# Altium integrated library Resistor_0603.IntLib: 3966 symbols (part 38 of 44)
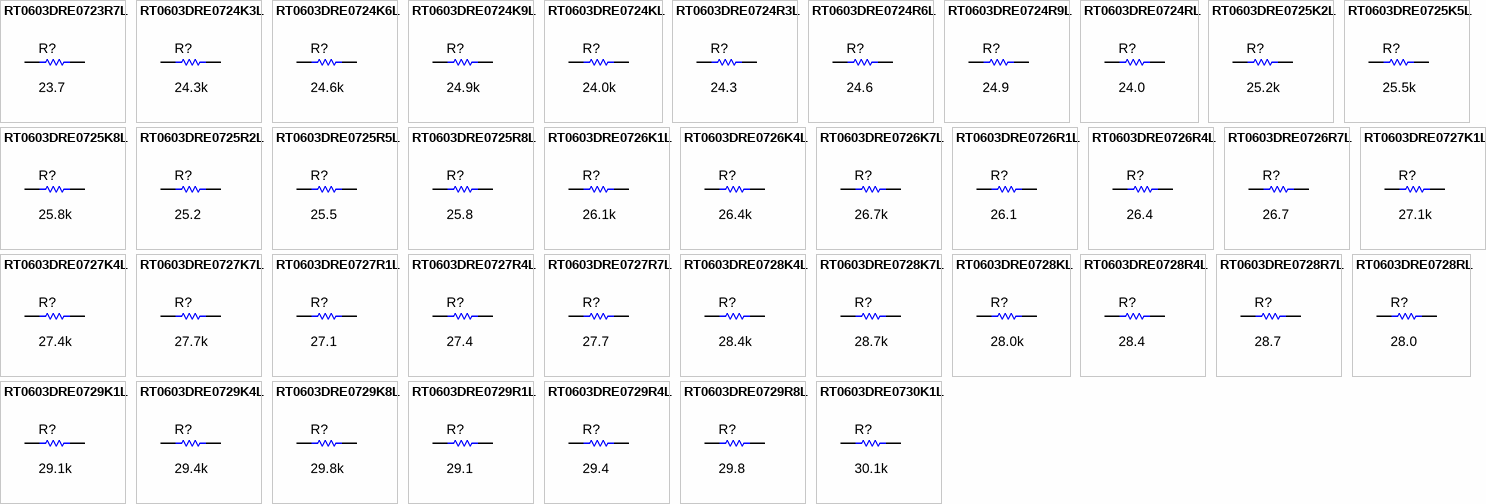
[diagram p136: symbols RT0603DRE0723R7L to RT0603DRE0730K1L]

## RT0603DRE0726R4L
designator R?  ValueDisplayed: 26.4  (hidden comment: RT0603DRE0726R4L)
RES, 26.4, 0.5%, 0.1 W, 0603; Manufacturer: Yageo America; CompType: Resistor; Value: 26.4; Value_Code: 26R4; Tolerance_%: 0.5; Power_W: 0.1; Value2: 0.1W; VDC_V: 75; TempCo: 50 ppm/C; SizeArea_mm2: 1.28; SizeX_mm: 1.6; SizeY_mm: 0.8; SizeZ_mm: 1; EIA_Code: E192; U/M: EA; AEC Category: Q200
signal-integrity model Resistor
simulation model Resistor
footprint 0603
footprint 0603M
footprint 0603L
footprint 0603_HV
footprint 0603S
pins: 1, 2

## RT0603DRE0726R7L
designator R?  ValueDisplayed: 26.7  (hidden comment: RT0603DRE0726R7L)
RES, 26.7, 0.5%, 0.1 W, 0603; Manufacturer: Yageo America; CompType: Resistor; Value: 26.7; Value_Code: 26R7; Tolerance_%: 0.5; Power_W: 0.1; Value2: 0.1W; VDC_V: 75; TempCo: 50 ppm/C; SizeArea_mm2: 1.28; SizeX_mm: 1.6; SizeY_mm: 0.8; SizeZ_mm: 1; EIA_Code: E192; U/M: EA; AEC Category: Q200
signal-integrity model Resistor
simulation model Resistor
footprint 0603
footprint 0603M
footprint 0603L
footprint 0603_HV
footprint 0603S
pins: 1, 2

## RT0603DRE0727K1L
designator R?  ValueDisplayed: 27.1k  (hidden comment: RT0603DRE0727K1L)
RES, 27.1 k, 0.5%, 0.1 W, 0603; Manufacturer: Yageo America; CompType: Resistor; Value: 27.1k; Res_ohm: 27100; Value_Code: 27k1; Tolerance_%: 0.5; Power_W: 0.1; Value2: 0.1W; VDC_V: 75; TempCo: 50 ppm/C; SizeArea_mm2: 1.28; SizeX_mm: 1.6; SizeY_mm: 0.8; SizeZ_mm: 1; EIA_Code: E192; U/M: EA; AEC Category: Q200
signal-integrity model Resistor
simulation model Resistor
footprint 0603
footprint 0603M
footprint 0603L
footprint 0603_HV
footprint 0603S
pins: 1, 2

## RT0603DRE0727K4L
designator R?  ValueDisplayed: 27.4k  (hidden comment: RT0603DRE0727K4L)
RES, 27.4 k, 0.5%, 0.1 W, 0603; Manufacturer: Yageo America; CompType: Resistor; Value: 27.4k; Res_ohm: 27400; Value_Code: 27k4; Tolerance_%: 0.5; Power_W: 0.1; Value2: 0.1W; VDC_V: 75; TempCo: 50 ppm/C; SizeArea_mm2: 1.28; SizeX_mm: 1.6; SizeY_mm: 0.8; SizeZ_mm: 1; EIA_Code: E192; U/M: EA; AEC Category: Q200
signal-integrity model Resistor
simulation model Resistor
footprint 0603
footprint 0603M
footprint 0603L
footprint 0603_HV
footprint 0603S
pins: 1, 2

## RT0603DRE0727K7L
designator R?  ValueDisplayed: 27.7k  (hidden comment: RT0603DRE0727K7L)
RES, 27.7 k, 0.5%, 0.1 W, 0603; Manufacturer: Yageo America; CompType: Resistor; Value: 27.7k; Res_ohm: 27700; Value_Code: 27k7; Tolerance_%: 0.5; Power_W: 0.1; Value2: 0.1W; VDC_V: 75; TempCo: 50 ppm/C; SizeArea_mm2: 1.28; SizeX_mm: 1.6; SizeY_mm: 0.8; SizeZ_mm: 1; EIA_Code: E192; U/M: EA; AEC Category: Q200
signal-integrity model Resistor
simulation model Resistor
footprint 0603
footprint 0603M
footprint 0603L
footprint 0603_HV
footprint 0603S
pins: 1, 2

## RT0603DRE0727R1L
designator R?  ValueDisplayed: 27.1  (hidden comment: RT0603DRE0727R1L)
RES, 27.1, 0.5%, 0.1 W, 0603; Manufacturer: Yageo America; CompType: Resistor; Value: 27.1; Value_Code: 27R1; Tolerance_%: 0.5; Power_W: 0.1; Value2: 0.1W; VDC_V: 75; TempCo: 50 ppm/C; SizeArea_mm2: 1.28; SizeX_mm: 1.6; SizeY_mm: 0.8; SizeZ_mm: 1; EIA_Code: E192; U/M: EA; AEC Category: Q200
signal-integrity model Resistor
simulation model Resistor
footprint 0603
footprint 0603M
footprint 0603L
footprint 0603_HV
footprint 0603S
pins: 1, 2

## RT0603DRE0727R4L
designator R?  ValueDisplayed: 27.4  (hidden comment: RT0603DRE0727R4L)
RES, 27.4, 0.5%, 0.1 W, 0603; Manufacturer: Yageo America; CompType: Resistor; Value: 27.4; Value_Code: 27R4; Tolerance_%: 0.5; Power_W: 0.1; Value2: 0.1W; VDC_V: 75; TempCo: 50 ppm/C; SizeArea_mm2: 1.28; SizeX_mm: 1.6; SizeY_mm: 0.8; SizeZ_mm: 1; EIA_Code: E192; U/M: EA; AEC Category: Q200
signal-integrity model Resistor
simulation model Resistor
footprint 0603
footprint 0603M
footprint 0603L
footprint 0603_HV
footprint 0603S
pins: 1, 2

## RT0603DRE0727R7L
designator R?  ValueDisplayed: 27.7  (hidden comment: RT0603DRE0727R7L)
RES, 27.7, 0.5%, 0.1 W, 0603; Manufacturer: Yageo America; CompType: Resistor; Value: 27.7; Value_Code: 27R7; Tolerance_%: 0.5; Power_W: 0.1; Value2: 0.1W; VDC_V: 75; TempCo: 50 ppm/C; SizeArea_mm2: 1.28; SizeX_mm: 1.6; SizeY_mm: 0.8; SizeZ_mm: 1; EIA_Code: E192; U/M: EA; AEC Category: Q200
signal-integrity model Resistor
simulation model Resistor
footprint 0603
footprint 0603M
footprint 0603L
footprint 0603_HV
footprint 0603S
pins: 1, 2

## RT0603DRE0728K4L
designator R?  ValueDisplayed: 28.4k  (hidden comment: RT0603DRE0728K4L)
RES, 28.4 k, 0.5%, 0.1 W, 0603; Manufacturer: Yageo America; CompType: Resistor; Value: 28.4k; Res_ohm: 28400; Value_Code: 28k4; Tolerance_%: 0.5; Power_W: 0.1; Value2: 0.1W; VDC_V: 75; TempCo: 50 ppm/C; SizeArea_mm2: 1.28; SizeX_mm: 1.6; SizeY_mm: 0.8; SizeZ_mm: 1; EIA_Code: E192; U/M: EA; AEC Category: Q200
signal-integrity model Resistor
simulation model Resistor
footprint 0603
footprint 0603M
footprint 0603L
footprint 0603_HV
footprint 0603S
pins: 1, 2

## RT0603DRE0728K7L
designator R?  ValueDisplayed: 28.7k  (hidden comment: RT0603DRE0728K7L)
RES, 28.7 k, 0.5%, 0.1 W, 0603; Manufacturer: Yageo America; CompType: Resistor; Value: 28.7k; Res_ohm: 28700; Value_Code: 28k7; Tolerance_%: 0.5; Power_W: 0.1; Value2: 0.1W; VDC_V: 75; TempCo: 50 ppm/C; SizeArea_mm2: 1.28; SizeX_mm: 1.6; SizeY_mm: 0.8; SizeZ_mm: 1; EIA_Code: E192; U/M: EA; AEC Category: Q200
signal-integrity model Resistor
simulation model Resistor
footprint 0603
footprint 0603M
footprint 0603L
footprint 0603_HV
footprint 0603S
pins: 1, 2

## RT0603DRE0728KL
designator R?  ValueDisplayed: 28.0k  (hidden comment: RT0603DRE0728KL)
RES, 28.0 k, 0.5%, 0.1 W, 0603; Manufacturer: Yageo America; CompType: Resistor; Value: 28.0k; Res_ohm: 28000; Value_Code: 28k0; Tolerance_%: 0.5; Power_W: 0.1; Value2: 0.1W; VDC_V: 75; TempCo: 50 ppm/C; SizeArea_mm2: 1.28; SizeX_mm: 1.6; SizeY_mm: 0.8; SizeZ_mm: 1; EIA_Code: E192; U/M: EA; AEC Category: Q200
signal-integrity model Resistor
simulation model Resistor
footprint 0603
footprint 0603M
footprint 0603L
footprint 0603_HV
footprint 0603S
pins: 1, 2

## RT0603DRE0728R4L
designator R?  ValueDisplayed: 28.4  (hidden comment: RT0603DRE0728R4L)
RES, 28.4, 0.5%, 0.1 W, 0603; Manufacturer: Yageo America; CompType: Resistor; Value: 28.4; Value_Code: 28R4; Tolerance_%: 0.5; Power_W: 0.1; Value2: 0.1W; VDC_V: 75; TempCo: 50 ppm/C; SizeArea_mm2: 1.28; SizeX_mm: 1.6; SizeY_mm: 0.8; SizeZ_mm: 1; EIA_Code: E192; U/M: EA; AEC Category: Q200
signal-integrity model Resistor
simulation model Resistor
footprint 0603
footprint 0603M
footprint 0603L
footprint 0603_HV
footprint 0603S
pins: 1, 2

## RT0603DRE0728R7L
designator R?  ValueDisplayed: 28.7  (hidden comment: RT0603DRE0728R7L)
RES, 28.7, 0.5%, 0.1 W, 0603; Manufacturer: Yageo America; CompType: Resistor; Value: 28.7; Value_Code: 28R7; Tolerance_%: 0.5; Power_W: 0.1; Value2: 0.1W; VDC_V: 75; TempCo: 50 ppm/C; SizeArea_mm2: 1.28; SizeX_mm: 1.6; SizeY_mm: 0.8; SizeZ_mm: 1; EIA_Code: E192; U/M: EA; AEC Category: Q200
signal-integrity model Resistor
simulation model Resistor
footprint 0603
footprint 0603M
footprint 0603L
footprint 0603_HV
footprint 0603S
pins: 1, 2

## RT0603DRE0728RL
designator R?  ValueDisplayed: 28.0  (hidden comment: RT0603DRE0728RL)
RES, 28.0, 0.5%, 0.1 W, 0603; Manufacturer: Yageo America; CompType: Resistor; Value: 28.0; Res_ohm: 28; Value_Code: 28R0; Tolerance_%: 0.5; Power_W: 0.1; Value2: 0.1W; VDC_V: 75; TempCo: 50 ppm/C; SizeArea_mm2: 1.28; SizeX_mm: 1.6; SizeY_mm: 0.8; SizeZ_mm: 1; EIA_Code: E192; U/M: EA; AEC Category: Q200
signal-integrity model Resistor
simulation model Resistor
footprint 0603
footprint 0603M
footprint 0603L
footprint 0603_HV
footprint 0603S
pins: 1, 2

## RT0603DRE0729K1L
designator R?  ValueDisplayed: 29.1k  (hidden comment: RT0603DRE0729K1L)
RES, 29.1 k, 0.5%, 0.1 W, 0603; Manufacturer: Yageo America; CompType: Resistor; Value: 29.1k; Res_ohm: 29100; Value_Code: 29k1; Tolerance_%: 0.5; Power_W: 0.1; Value2: 0.1W; VDC_V: 75; TempCo: 50 ppm/C; SizeArea_mm2: 1.28; SizeX_mm: 1.6; SizeY_mm: 0.8; SizeZ_mm: 1; EIA_Code: E192; U/M: EA; AEC Category: Q200
signal-integrity model Resistor
simulation model Resistor
footprint 0603
footprint 0603M
footprint 0603L
footprint 0603_HV
footprint 0603S
pins: 1, 2

## RT0603DRE0729K4L
designator R?  ValueDisplayed: 29.4k  (hidden comment: RT0603DRE0729K4L)
RES, 29.4 k, 0.5%, 0.1 W, 0603; Manufacturer: Yageo America; CompType: Resistor; Value: 29.4k; Res_ohm: 29400; Value_Code: 29k4; Tolerance_%: 0.5; Power_W: 0.1; Value2: 0.1W; VDC_V: 75; TempCo: 50 ppm/C; SizeArea_mm2: 1.28; SizeX_mm: 1.6; SizeY_mm: 0.8; SizeZ_mm: 1; EIA_Code: E192; U/M: EA; AEC Category: Q200
signal-integrity model Resistor
simulation model Resistor
footprint 0603
footprint 0603M
footprint 0603L
footprint 0603_HV
footprint 0603S
pins: 1, 2

## RT0603DRE0729K8L
designator R?  ValueDisplayed: 29.8k  (hidden comment: RT0603DRE0729K8L)
RES, 29.8 k, 0.5%, 0.1 W, 0603; Manufacturer: Yageo America; CompType: Resistor; Value: 29.8k; Res_ohm: 29800; Value_Code: 29k8; Tolerance_%: 0.5; Power_W: 0.1; Value2: 0.1W; VDC_V: 75; TempCo: 50 ppm/C; SizeArea_mm2: 1.28; SizeX_mm: 1.6; SizeY_mm: 0.8; SizeZ_mm: 1; EIA_Code: E192; U/M: EA; AEC Category: Q200
signal-integrity model Resistor
simulation model Resistor
footprint 0603
footprint 0603M
footprint 0603L
footprint 0603_HV
footprint 0603S
pins: 1, 2

## RT0603DRE0729R1L
designator R?  ValueDisplayed: 29.1  (hidden comment: RT0603DRE0729R1L)
RES, 29.1, 0.5%, 0.1 W, 0603; Manufacturer: Yageo America; CompType: Resistor; Value: 29.1; Value_Code: 29R1; Tolerance_%: 0.5; Power_W: 0.1; Value2: 0.1W; VDC_V: 75; TempCo: 50 ppm/C; SizeArea_mm2: 1.28; SizeX_mm: 1.6; SizeY_mm: 0.8; SizeZ_mm: 1; EIA_Code: E192; U/M: EA; AEC Category: Q200
signal-integrity model Resistor
simulation model Resistor
footprint 0603
footprint 0603M
footprint 0603L
footprint 0603_HV
footprint 0603S
pins: 1, 2

## RT0603DRE0729R4L
designator R?  ValueDisplayed: 29.4  (hidden comment: RT0603DRE0729R4L)
RES, 29.4, 0.5%, 0.1 W, 0603; Manufacturer: Yageo America; CompType: Resistor; Value: 29.4; Value_Code: 29R4; Tolerance_%: 0.5; Power_W: 0.1; Value2: 0.1W; VDC_V: 75; TempCo: 50 ppm/C; SizeArea_mm2: 1.28; SizeX_mm: 1.6; SizeY_mm: 0.8; SizeZ_mm: 1; EIA_Code: E192; U/M: EA; AEC Category: Q200
signal-integrity model Resistor
simulation model Resistor
footprint 0603
footprint 0603M
footprint 0603L
footprint 0603_HV
footprint 0603S
pins: 1, 2

## RT0603DRE0729R8L
designator R?  ValueDisplayed: 29.8  (hidden comment: RT0603DRE0729R8L)
RES, 29.8, 0.5%, 0.1 W, 0603; Manufacturer: Yageo America; CompType: Resistor; Value: 29.8; Value_Code: 29R8; Tolerance_%: 0.5; Power_W: 0.1; Value2: 0.1W; VDC_V: 75; TempCo: 50 ppm/C; SizeArea_mm2: 1.28; SizeX_mm: 1.6; SizeY_mm: 0.8; SizeZ_mm: 1; EIA_Code: E192; U/M: EA; AEC Category: Q200
signal-integrity model Resistor
simulation model Resistor
footprint 0603
footprint 0603M
footprint 0603L
footprint 0603_HV
footprint 0603S
pins: 1, 2

## RT0603DRE0730K1L
designator R?  ValueDisplayed: 30.1k  (hidden comment: RT0603DRE0730K1L)
RES, 30.1 k, 0.5%, 0.1 W, 0603; Manufacturer: Yageo America; CompType: Resistor; Value: 30.1k; Res_ohm: 30100; Value_Code: 30k1; Tolerance_%: 0.5; Power_W: 0.1; Value2: 0.1W; VDC_V: 75; TempCo: 50 ppm/C; SizeArea_mm2: 1.28; SizeX_mm: 1.6; SizeY_mm: 0.8; SizeZ_mm: 1; EIA_Code: E192; U/M: EA; AEC Category: Q200
signal-integrity model Resistor
simulation model Resistor
footprint 0603
footprint 0603M
footprint 0603L
footprint 0603_HV
footprint 0603S
pins: 1, 2

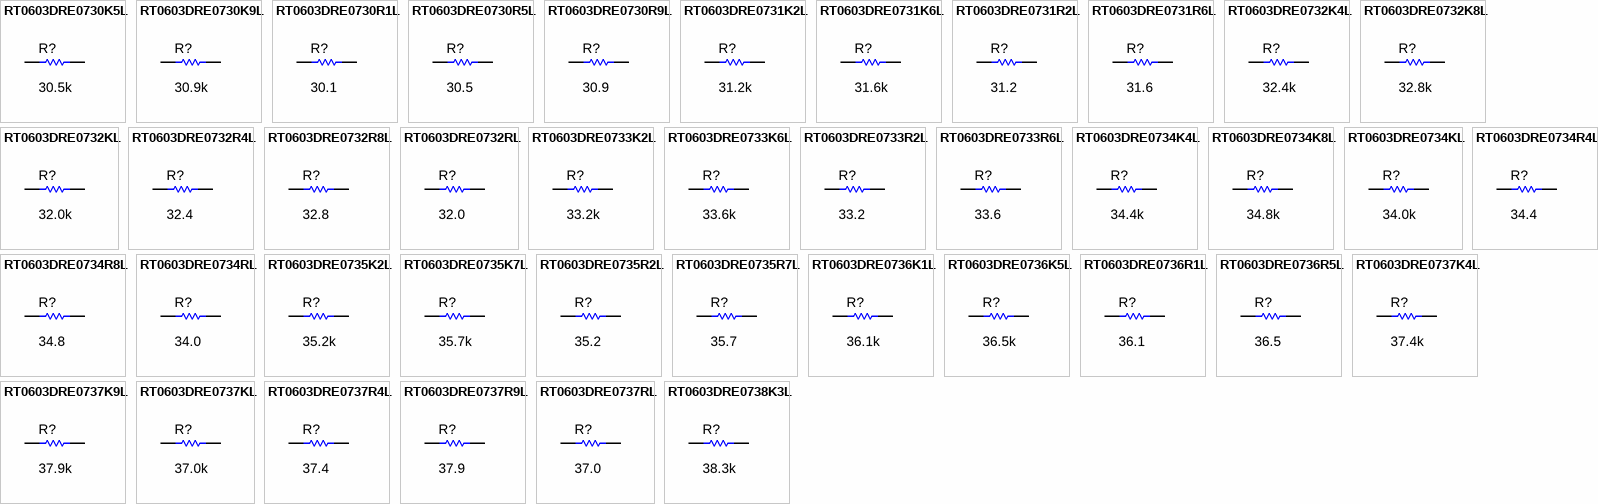
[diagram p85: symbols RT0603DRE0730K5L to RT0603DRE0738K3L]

## RT0603DRE0730K5L
designator R?  ValueDisplayed: 30.5k  (hidden comment: RT0603DRE0730K5L)
RES, 30.5 k, 0.5%, 0.1 W, 0603; Manufacturer: Yageo America; CompType: Resistor; Value: 30.5k; Res_ohm: 30500; Value_Code: 30k5; Tolerance_%: 0.5; Power_W: 0.1; Value2: 0.1W; VDC_V: 75; TempCo: 50 ppm/C; SizeArea_mm2: 1.28; SizeX_mm: 1.6; SizeY_mm: 0.8; SizeZ_mm: 1; EIA_Code: E192; U/M: EA; AEC Category: Q200
signal-integrity model Resistor
simulation model Resistor
footprint 0603
footprint 0603M
footprint 0603L
footprint 0603_HV
footprint 0603S
pins: 1, 2

## RT0603DRE0730K9L
designator R?  ValueDisplayed: 30.9k  (hidden comment: RT0603DRE0730K9L)
RES, 30.9 k, 0.5%, 0.1 W, 0603; Manufacturer: Yageo America; CompType: Resistor; Value: 30.9k; Res_ohm: 30900; Value_Code: 30k9; Tolerance_%: 0.5; Power_W: 0.1; Value2: 0.1W; VDC_V: 75; TempCo: 50 ppm/C; SizeArea_mm2: 1.28; SizeX_mm: 1.6; SizeY_mm: 0.8; SizeZ_mm: 1; EIA_Code: E192; U/M: EA; AEC Category: Q200
signal-integrity model Resistor
simulation model Resistor
footprint 0603
footprint 0603M
footprint 0603L
footprint 0603_HV
footprint 0603S
pins: 1, 2

## RT0603DRE0730R1L
designator R?  ValueDisplayed: 30.1  (hidden comment: RT0603DRE0730R1L)
RES, 30.1, 0.5%, 0.1 W, 0603; Manufacturer: Yageo America; CompType: Resistor; Value: 30.1; Value_Code: 30R1; Tolerance_%: 0.5; Power_W: 0.1; Value2: 0.1W; VDC_V: 75; TempCo: 50 ppm/C; SizeArea_mm2: 1.28; SizeX_mm: 1.6; SizeY_mm: 0.8; SizeZ_mm: 1; EIA_Code: E192; U/M: EA; AEC Category: Q200
signal-integrity model Resistor
simulation model Resistor
footprint 0603
footprint 0603M
footprint 0603L
footprint 0603_HV
footprint 0603S
pins: 1, 2

## RT0603DRE0730R5L
designator R?  ValueDisplayed: 30.5  (hidden comment: RT0603DRE0730R5L)
RES, 30.5, 0.5%, 0.1 W, 0603; Manufacturer: Yageo America; CompType: Resistor; Value: 30.5; Value_Code: 30R5; Tolerance_%: 0.5; Power_W: 0.1; Value2: 0.1W; VDC_V: 75; TempCo: 50 ppm/C; SizeArea_mm2: 1.28; SizeX_mm: 1.6; SizeY_mm: 0.8; SizeZ_mm: 1; EIA_Code: E192; U/M: EA; AEC Category: Q200
signal-integrity model Resistor
simulation model Resistor
footprint 0603
footprint 0603M
footprint 0603L
footprint 0603_HV
footprint 0603S
pins: 1, 2

## RT0603DRE0730R9L
designator R?  ValueDisplayed: 30.9  (hidden comment: RT0603DRE0730R9L)
RES, 30.9, 0.5%, 0.1 W, 0603; Manufacturer: Yageo America; CompType: Resistor; Value: 30.9; Value_Code: 30R9; Tolerance_%: 0.5; Power_W: 0.1; Value2: 0.1W; VDC_V: 75; TempCo: 50 ppm/C; SizeArea_mm2: 1.28; SizeX_mm: 1.6; SizeY_mm: 0.8; SizeZ_mm: 1; EIA_Code: E192; U/M: EA; AEC Category: Q200
signal-integrity model Resistor
simulation model Resistor
footprint 0603
footprint 0603M
footprint 0603L
footprint 0603_HV
footprint 0603S
pins: 1, 2

## RT0603DRE0731K2L
designator R?  ValueDisplayed: 31.2k  (hidden comment: RT0603DRE0731K2L)
RES, 31.2 k, 0.5%, 0.1 W, 0603; Manufacturer: Yageo America; CompType: Resistor; Value: 31.2k; Res_ohm: 31200; Value_Code: 31k2; Tolerance_%: 0.5; Power_W: 0.1; Value2: 0.1W; VDC_V: 75; TempCo: 50 ppm/C; SizeArea_mm2: 1.28; SizeX_mm: 1.6; SizeY_mm: 0.8; SizeZ_mm: 1; EIA_Code: E192; U/M: EA; AEC Category: Q200
signal-integrity model Resistor
simulation model Resistor
footprint 0603
footprint 0603M
footprint 0603L
footprint 0603_HV
footprint 0603S
pins: 1, 2

## RT0603DRE0731K6L
designator R?  ValueDisplayed: 31.6k  (hidden comment: RT0603DRE0731K6L)
RES, 31.6 k, 0.5%, 0.1 W, 0603; Manufacturer: Yageo America; CompType: Resistor; Value: 31.6k; Res_ohm: 31600; Value_Code: 31k6; Tolerance_%: 0.5; Power_W: 0.1; Value2: 0.1W; VDC_V: 75; TempCo: 50 ppm/C; SizeArea_mm2: 1.28; SizeX_mm: 1.6; SizeY_mm: 0.8; SizeZ_mm: 1; EIA_Code: E192; U/M: EA; AEC Category: Q200
signal-integrity model Resistor
simulation model Resistor
footprint 0603
footprint 0603M
footprint 0603L
footprint 0603_HV
footprint 0603S
pins: 1, 2

## RT0603DRE0731R2L
designator R?  ValueDisplayed: 31.2  (hidden comment: RT0603DRE0731R2L)
RES, 31.2, 0.5%, 0.1 W, 0603; Manufacturer: Yageo America; CompType: Resistor; Value: 31.2; Value_Code: 31R2; Tolerance_%: 0.5; Power_W: 0.1; Value2: 0.1W; VDC_V: 75; TempCo: 50 ppm/C; SizeArea_mm2: 1.28; SizeX_mm: 1.6; SizeY_mm: 0.8; SizeZ_mm: 1; EIA_Code: E192; U/M: EA; AEC Category: Q200
signal-integrity model Resistor
simulation model Resistor
footprint 0603
footprint 0603M
footprint 0603L
footprint 0603_HV
footprint 0603S
pins: 1, 2

## RT0603DRE0731R6L
designator R?  ValueDisplayed: 31.6  (hidden comment: RT0603DRE0731R6L)
RES, 31.6, 0.5%, 0.1 W, 0603; Manufacturer: Yageo America; CompType: Resistor; Value: 31.6; Value_Code: 31R6; Tolerance_%: 0.5; Power_W: 0.1; Value2: 0.1W; VDC_V: 75; TempCo: 50 ppm/C; SizeArea_mm2: 1.28; SizeX_mm: 1.6; SizeY_mm: 0.8; SizeZ_mm: 1; EIA_Code: E192; U/M: EA; AEC Category: Q200
signal-integrity model Resistor
simulation model Resistor
footprint 0603
footprint 0603M
footprint 0603L
footprint 0603_HV
footprint 0603S
pins: 1, 2

## RT0603DRE0732K4L
designator R?  ValueDisplayed: 32.4k  (hidden comment: RT0603DRE0732K4L)
RES, 32.4 k, 0.5%, 0.1 W, 0603; Manufacturer: Yageo America; CompType: Resistor; Value: 32.4k; Res_ohm: 32400; Value_Code: 32k4; Tolerance_%: 0.5; Power_W: 0.1; Value2: 0.1W; VDC_V: 75; TempCo: 50 ppm/C; SizeArea_mm2: 1.28; SizeX_mm: 1.6; SizeY_mm: 0.8; SizeZ_mm: 1; EIA_Code: E192; U/M: EA; AEC Category: Q200
signal-integrity model Resistor
simulation model Resistor
footprint 0603
footprint 0603M
footprint 0603L
footprint 0603_HV
footprint 0603S
pins: 1, 2

## RT0603DRE0732K8L
designator R?  ValueDisplayed: 32.8k  (hidden comment: RT0603DRE0732K8L)
RES, 32.8 k, 0.5%, 0.1 W, 0603; Manufacturer: Yageo America; CompType: Resistor; Value: 32.8k; Res_ohm: 32800; Value_Code: 32k8; Tolerance_%: 0.5; Power_W: 0.1; Value2: 0.1W; VDC_V: 75; TempCo: 50 ppm/C; SizeArea_mm2: 1.28; SizeX_mm: 1.6; SizeY_mm: 0.8; SizeZ_mm: 1; EIA_Code: E192; U/M: EA; AEC Category: Q200
signal-integrity model Resistor
simulation model Resistor
footprint 0603
footprint 0603M
footprint 0603L
footprint 0603_HV
footprint 0603S
pins: 1, 2

## RT0603DRE0732KL
designator R?  ValueDisplayed: 32.0k  (hidden comment: RT0603DRE0732KL)
RES, 32.0 k, 0.5%, 0.1 W, 0603; Manufacturer: Yageo America; CompType: Resistor; Value: 32.0k; Res_ohm: 32000; Value_Code: 32k0; Tolerance_%: 0.5; Power_W: 0.1; Value2: 0.1W; VDC_V: 75; TempCo: 50 ppm/C; SizeArea_mm2: 1.28; SizeX_mm: 1.6; SizeY_mm: 0.8; SizeZ_mm: 1; EIA_Code: E192; U/M: EA; AEC Category: Q200
signal-integrity model Resistor
simulation model Resistor
footprint 0603
footprint 0603M
footprint 0603L
footprint 0603_HV
footprint 0603S
pins: 1, 2

## RT0603DRE0732R4L
designator R?  ValueDisplayed: 32.4  (hidden comment: RT0603DRE0732R4L)
RES, 32.4, 0.5%, 0.1 W, 0603; Manufacturer: Yageo America; CompType: Resistor; Value: 32.4; Value_Code: 32R4; Tolerance_%: 0.5; Power_W: 0.1; Value2: 0.1W; VDC_V: 75; TempCo: 50 ppm/C; SizeArea_mm2: 1.28; SizeX_mm: 1.6; SizeY_mm: 0.8; SizeZ_mm: 1; EIA_Code: E192; U/M: EA; AEC Category: Q200
signal-integrity model Resistor
simulation model Resistor
footprint 0603
footprint 0603M
footprint 0603L
footprint 0603_HV
footprint 0603S
pins: 1, 2

## RT0603DRE0732R8L
designator R?  ValueDisplayed: 32.8  (hidden comment: RT0603DRE0732R8L)
RES, 32.8, 0.5%, 0.1 W, 0603; Manufacturer: Yageo America; CompType: Resistor; Value: 32.8; Value_Code: 32R8; Tolerance_%: 0.5; Power_W: 0.1; Value2: 0.1W; VDC_V: 75; TempCo: 50 ppm/C; SizeArea_mm2: 1.28; SizeX_mm: 1.6; SizeY_mm: 0.8; SizeZ_mm: 1; EIA_Code: E192; U/M: EA; AEC Category: Q200
signal-integrity model Resistor
simulation model Resistor
footprint 0603
footprint 0603M
footprint 0603L
footprint 0603_HV
footprint 0603S
pins: 1, 2

## RT0603DRE0732RL
designator R?  ValueDisplayed: 32.0  (hidden comment: RT0603DRE0732RL)
RES, 32.0, 0.5%, 0.1 W, 0603; Manufacturer: Yageo America; CompType: Resistor; Value: 32.0; Res_ohm: 32; Value_Code: 32R0; Tolerance_%: 0.5; Power_W: 0.1; Value2: 0.1W; VDC_V: 75; TempCo: 50 ppm/C; SizeArea_mm2: 1.28; SizeX_mm: 1.6; SizeY_mm: 0.8; SizeZ_mm: 1; EIA_Code: E192; U/M: EA; AEC Category: Q200
signal-integrity model Resistor
simulation model Resistor
footprint 0603
footprint 0603M
footprint 0603L
footprint 0603_HV
footprint 0603S
pins: 1, 2

## RT0603DRE0733K2L
designator R?  ValueDisplayed: 33.2k  (hidden comment: RT0603DRE0733K2L)
RES, 33.2 k, 0.5%, 0.1 W, 0603; Manufacturer: Yageo America; CompType: Resistor; Value: 33.2k; Res_ohm: 33200; Value_Code: 33k2; Tolerance_%: 0.5; Power_W: 0.1; Value2: 0.1W; VDC_V: 75; TempCo: 50 ppm/C; SizeArea_mm2: 1.28; SizeX_mm: 1.6; SizeY_mm: 0.8; SizeZ_mm: 1; EIA_Code: E192; U/M: EA; AEC Category: Q200
signal-integrity model Resistor
simulation model Resistor
footprint 0603
footprint 0603M
footprint 0603L
footprint 0603_HV
footprint 0603S
pins: 1, 2

## RT0603DRE0733K6L
designator R?  ValueDisplayed: 33.6k  (hidden comment: RT0603DRE0733K6L)
RES, 33.6 k, 0.5%, 0.1 W, 0603; Manufacturer: Yageo America; CompType: Resistor; Value: 33.6k; Res_ohm: 33600; Value_Code: 33k6; Tolerance_%: 0.5; Power_W: 0.1; Value2: 0.1W; VDC_V: 75; TempCo: 50 ppm/C; SizeArea_mm2: 1.28; SizeX_mm: 1.6; SizeY_mm: 0.8; SizeZ_mm: 1; EIA_Code: E192; U/M: EA; AEC Category: Q200
signal-integrity model Resistor
simulation model Resistor
footprint 0603
footprint 0603M
footprint 0603L
footprint 0603_HV
footprint 0603S
pins: 1, 2

## RT0603DRE0733R2L
designator R?  ValueDisplayed: 33.2  (hidden comment: RT0603DRE0733R2L)
RES, 33.2, 0.5%, 0.1 W, 0603; Manufacturer: Yageo America; CompType: Resistor; Value: 33.2; Value_Code: 33R2; Tolerance_%: 0.5; Power_W: 0.1; Value2: 0.1W; VDC_V: 75; TempCo: 50 ppm/C; SizeArea_mm2: 1.28; SizeX_mm: 1.6; SizeY_mm: 0.8; SizeZ_mm: 1; EIA_Code: E192; U/M: EA; AEC Category: Q200
signal-integrity model Resistor
simulation model Resistor
footprint 0603
footprint 0603M
footprint 0603L
footprint 0603_HV
footprint 0603S
pins: 1, 2

## RT0603DRE0733R6L
designator R?  ValueDisplayed: 33.6  (hidden comment: RT0603DRE0733R6L)
RES, 33.6, 0.5%, 0.1 W, 0603; Manufacturer: Yageo America; CompType: Resistor; Value: 33.6; Value_Code: 33R6; Tolerance_%: 0.5; Power_W: 0.1; Value2: 0.1W; VDC_V: 75; TempCo: 50 ppm/C; SizeArea_mm2: 1.28; SizeX_mm: 1.6; SizeY_mm: 0.8; SizeZ_mm: 1; EIA_Code: E192; U/M: EA; AEC Category: Q200
signal-integrity model Resistor
simulation model Resistor
footprint 0603
footprint 0603M
footprint 0603L
footprint 0603_HV
footprint 0603S
pins: 1, 2

## RT0603DRE0734K4L
designator R?  ValueDisplayed: 34.4k  (hidden comment: RT0603DRE0734K4L)
RES, 34.4 k, 0.5%, 0.1 W, 0603; Manufacturer: Yageo America; CompType: Resistor; Value: 34.4k; Res_ohm: 34400; Value_Code: 34k4; Tolerance_%: 0.5; Power_W: 0.1; Value2: 0.1W; VDC_V: 75; TempCo: 50 ppm/C; SizeArea_mm2: 1.28; SizeX_mm: 1.6; SizeY_mm: 0.8; SizeZ_mm: 1; EIA_Code: E192; U/M: EA; AEC Category: Q200
signal-integrity model Resistor
simulation model Resistor
footprint 0603
footprint 0603M
footprint 0603L
footprint 0603_HV
footprint 0603S
pins: 1, 2

## RT0603DRE0734K8L
designator R?  ValueDisplayed: 34.8k  (hidden comment: RT0603DRE0734K8L)
RES, 34.8 k, 0.5%, 0.1 W, 0603; Manufacturer: Yageo America; CompType: Resistor; Value: 34.8k; Res_ohm: 34800; Value_Code: 34k8; Tolerance_%: 0.5; Power_W: 0.1; Value2: 0.1W; VDC_V: 75; TempCo: 50 ppm/C; SizeArea_mm2: 1.28; SizeX_mm: 1.6; SizeY_mm: 0.8; SizeZ_mm: 1; EIA_Code: E192; U/M: EA; AEC Category: Q200
signal-integrity model Resistor
simulation model Resistor
footprint 0603
footprint 0603M
footprint 0603L
footprint 0603_HV
footprint 0603S
pins: 1, 2

## RT0603DRE0734KL
designator R?  ValueDisplayed: 34.0k  (hidden comment: RT0603DRE0734KL)
RES, 34.0 k, 0.5%, 0.1 W, 0603; Manufacturer: Yageo America; CompType: Resistor; Value: 34.0k; Res_ohm: 34000; Value_Code: 34k0; Tolerance_%: 0.5; Power_W: 0.1; Value2: 0.1W; VDC_V: 75; TempCo: 50 ppm/C; SizeArea_mm2: 1.28; SizeX_mm: 1.6; SizeY_mm: 0.8; SizeZ_mm: 1; EIA_Code: E192; U/M: EA; AEC Category: Q200
signal-integrity model Resistor
simulation model Resistor
footprint 0603
footprint 0603M
footprint 0603L
footprint 0603_HV
footprint 0603S
pins: 1, 2

## RT0603DRE0734R4L
designator R?  ValueDisplayed: 34.4  (hidden comment: RT0603DRE0734R4L)
RES, 34.4, 0.5%, 0.1 W, 0603; Manufacturer: Yageo America; CompType: Resistor; Value: 34.4; Value_Code: 34R4; Tolerance_%: 0.5; Power_W: 0.1; Value2: 0.1W; VDC_V: 75; TempCo: 50 ppm/C; SizeArea_mm2: 1.28; SizeX_mm: 1.6; SizeY_mm: 0.8; SizeZ_mm: 1; EIA_Code: E192; U/M: EA; AEC Category: Q200
signal-integrity model Resistor
simulation model Resistor
footprint 0603
footprint 0603M
footprint 0603L
footprint 0603_HV
footprint 0603S
pins: 1, 2

## RT0603DRE0734R8L
designator R?  ValueDisplayed: 34.8  (hidden comment: RT0603DRE0734R8L)
RES, 34.8, 0.5%, 0.1 W, 0603; Manufacturer: Yageo America; CompType: Resistor; Value: 34.8; Value_Code: 34R8; Tolerance_%: 0.5; Power_W: 0.1; Value2: 0.1W; VDC_V: 75; TempCo: 50 ppm/C; SizeArea_mm2: 1.28; SizeX_mm: 1.6; SizeY_mm: 0.8; SizeZ_mm: 1; EIA_Code: E192; U/M: EA; AEC Category: Q200
signal-integrity model Resistor
simulation model Resistor
footprint 0603
footprint 0603M
footprint 0603L
footprint 0603_HV
footprint 0603S
pins: 1, 2

## RT0603DRE0734RL
designator R?  ValueDisplayed: 34.0  (hidden comment: RT0603DRE0734RL)
RES, 34.0, 0.5%, 0.1 W, 0603; Manufacturer: Yageo America; CompType: Resistor; Value: 34.0; Res_ohm: 34; Value_Code: 34R0; Tolerance_%: 0.5; Power_W: 0.1; Value2: 0.1W; VDC_V: 75; TempCo: 50 ppm/C; SizeArea_mm2: 1.28; SizeX_mm: 1.6; SizeY_mm: 0.8; SizeZ_mm: 1; EIA_Code: E192; U/M: EA; AEC Category: Q200
signal-integrity model Resistor
simulation model Resistor
footprint 0603
footprint 0603M
footprint 0603L
footprint 0603_HV
footprint 0603S
pins: 1, 2

## RT0603DRE0735K2L
designator R?  ValueDisplayed: 35.2k  (hidden comment: RT0603DRE0735K2L)
RES, 35.2 k, 0.5%, 0.1 W, 0603; Manufacturer: Yageo America; CompType: Resistor; Value: 35.2k; Res_ohm: 35200; Value_Code: 35k2; Tolerance_%: 0.5; Power_W: 0.1; Value2: 0.1W; VDC_V: 75; TempCo: 50 ppm/C; SizeArea_mm2: 1.28; SizeX_mm: 1.6; SizeY_mm: 0.8; SizeZ_mm: 1; EIA_Code: E192; U/M: EA; AEC Category: Q200
signal-integrity model Resistor
simulation model Resistor
footprint 0603
footprint 0603M
footprint 0603L
footprint 0603_HV
footprint 0603S
pins: 1, 2

## RT0603DRE0735K7L
designator R?  ValueDisplayed: 35.7k  (hidden comment: RT0603DRE0735K7L)
RES, 35.7 k, 0.5%, 0.1 W, 0603; Manufacturer: Yageo America; CompType: Resistor; Value: 35.7k; Res_ohm: 35700; Value_Code: 35k7; Tolerance_%: 0.5; Power_W: 0.1; Value2: 0.1W; VDC_V: 75; TempCo: 50 ppm/C; SizeArea_mm2: 1.28; SizeX_mm: 1.6; SizeY_mm: 0.8; SizeZ_mm: 1; EIA_Code: E192; U/M: EA; AEC Category: Q200
signal-integrity model Resistor
simulation model Resistor
footprint 0603
footprint 0603M
footprint 0603L
footprint 0603_HV
footprint 0603S
pins: 1, 2

## RT0603DRE0735R2L
designator R?  ValueDisplayed: 35.2  (hidden comment: RT0603DRE0735R2L)
RES, 35.2, 0.5%, 0.1 W, 0603; Manufacturer: Yageo America; CompType: Resistor; Value: 35.2; Value_Code: 35R2; Tolerance_%: 0.5; Power_W: 0.1; Value2: 0.1W; VDC_V: 75; TempCo: 50 ppm/C; SizeArea_mm2: 1.28; SizeX_mm: 1.6; SizeY_mm: 0.8; SizeZ_mm: 1; EIA_Code: E192; U/M: EA; AEC Category: Q200
signal-integrity model Resistor
simulation model Resistor
footprint 0603
footprint 0603M
footprint 0603L
footprint 0603_HV
footprint 0603S
pins: 1, 2

## RT0603DRE0735R7L
designator R?  ValueDisplayed: 35.7  (hidden comment: RT0603DRE0735R7L)
RES, 35.7, 0.5%, 0.1 W, 0603; Manufacturer: Yageo America; CompType: Resistor; Value: 35.7; Value_Code: 35R7; Tolerance_%: 0.5; Power_W: 0.1; Value2: 0.1W; VDC_V: 75; TempCo: 50 ppm/C; SizeArea_mm2: 1.28; SizeX_mm: 1.6; SizeY_mm: 0.8; SizeZ_mm: 1; EIA_Code: E192; U/M: EA; AEC Category: Q200
signal-integrity model Resistor
simulation model Resistor
footprint 0603
footprint 0603M
footprint 0603L
footprint 0603_HV
footprint 0603S
pins: 1, 2

## RT0603DRE0736K1L
designator R?  ValueDisplayed: 36.1k  (hidden comment: RT0603DRE0736K1L)
RES, 36.1 k, 0.5%, 0.1 W, 0603; Manufacturer: Yageo America; CompType: Resistor; Value: 36.1k; Res_ohm: 36100; Value_Code: 36k1; Tolerance_%: 0.5; Power_W: 0.1; Value2: 0.1W; VDC_V: 75; TempCo: 50 ppm/C; SizeArea_mm2: 1.28; SizeX_mm: 1.6; SizeY_mm: 0.8; SizeZ_mm: 1; EIA_Code: E192; U/M: EA; AEC Category: Q200
signal-integrity model Resistor
simulation model Resistor
footprint 0603
footprint 0603M
footprint 0603L
footprint 0603_HV
footprint 0603S
pins: 1, 2

## RT0603DRE0736K5L
designator R?  ValueDisplayed: 36.5k  (hidden comment: RT0603DRE0736K5L)
RES, 36.5 k, 0.5%, 0.1 W, 0603; Manufacturer: Yageo America; CompType: Resistor; Value: 36.5k; Res_ohm: 36500; Value_Code: 36k5; Tolerance_%: 0.5; Power_W: 0.1; Value2: 0.1W; VDC_V: 75; TempCo: 50 ppm/C; SizeArea_mm2: 1.28; SizeX_mm: 1.6; SizeY_mm: 0.8; SizeZ_mm: 1; EIA_Code: E192; U/M: EA; AEC Category: Q200
signal-integrity model Resistor
simulation model Resistor
footprint 0603
footprint 0603M
footprint 0603L
footprint 0603_HV
footprint 0603S
pins: 1, 2

## RT0603DRE0736R1L
designator R?  ValueDisplayed: 36.1  (hidden comment: RT0603DRE0736R1L)
RES, 36.1, 0.5%, 0.1 W, 0603; Manufacturer: Yageo America; CompType: Resistor; Value: 36.1; Value_Code: 36R1; Tolerance_%: 0.5; Power_W: 0.1; Value2: 0.1W; VDC_V: 75; TempCo: 50 ppm/C; SizeArea_mm2: 1.28; SizeX_mm: 1.6; SizeY_mm: 0.8; SizeZ_mm: 1; EIA_Code: E192; U/M: EA; AEC Category: Q200
signal-integrity model Resistor
simulation model Resistor
footprint 0603
footprint 0603M
footprint 0603L
footprint 0603_HV
footprint 0603S
pins: 1, 2

## RT0603DRE0736R5L
designator R?  ValueDisplayed: 36.5  (hidden comment: RT0603DRE0736R5L)
RES, 36.5, 0.5%, 0.1 W, 0603; Manufacturer: Yageo America; CompType: Resistor; Value: 36.5; Value_Code: 36R5; Tolerance_%: 0.5; Power_W: 0.1; Value2: 0.1W; VDC_V: 75; TempCo: 50 ppm/C; SizeArea_mm2: 1.28; SizeX_mm: 1.6; SizeY_mm: 0.8; SizeZ_mm: 1; EIA_Code: E192; U/M: EA; AEC Category: Q200
signal-integrity model Resistor
simulation model Resistor
footprint 0603
footprint 0603M
footprint 0603L
footprint 0603_HV
footprint 0603S
pins: 1, 2

## RT0603DRE0737K4L
designator R?  ValueDisplayed: 37.4k  (hidden comment: RT0603DRE0737K4L)
RES, 37.4 k, 0.5%, 0.1 W, 0603; Manufacturer: Yageo America; CompType: Resistor; Value: 37.4k; Res_ohm: 37400; Value_Code: 37k4; Tolerance_%: 0.5; Power_W: 0.1; Value2: 0.1W; VDC_V: 75; TempCo: 50 ppm/C; SizeArea_mm2: 1.28; SizeX_mm: 1.6; SizeY_mm: 0.8; SizeZ_mm: 1; EIA_Code: E192; U/M: EA; AEC Category: Q200
signal-integrity model Resistor
simulation model Resistor
footprint 0603
footprint 0603M
footprint 0603L
footprint 0603_HV
footprint 0603S
pins: 1, 2

## RT0603DRE0737K9L
designator R?  ValueDisplayed: 37.9k  (hidden comment: RT0603DRE0737K9L)
RES, 37.9 k, 0.5%, 0.1 W, 0603; Manufacturer: Yageo America; CompType: Resistor; Value: 37.9k; Res_ohm: 37900; Value_Code: 37k9; Tolerance_%: 0.5; Power_W: 0.1; Value2: 0.1W; VDC_V: 75; TempCo: 50 ppm/C; SizeArea_mm2: 1.28; SizeX_mm: 1.6; SizeY_mm: 0.8; SizeZ_mm: 1; EIA_Code: E192; U/M: EA; AEC Category: Q200
signal-integrity model Resistor
simulation model Resistor
footprint 0603
footprint 0603M
footprint 0603L
footprint 0603_HV
footprint 0603S
pins: 1, 2

## RT0603DRE0737KL
designator R?  ValueDisplayed: 37.0k  (hidden comment: RT0603DRE0737KL)
RES, 37.0 k, 0.5%, 0.1 W, 0603; Manufacturer: Yageo America; CompType: Resistor; Value: 37.0k; Res_ohm: 37000; Value_Code: 37k0; Tolerance_%: 0.5; Power_W: 0.1; Value2: 0.1W; VDC_V: 75; TempCo: 50 ppm/C; SizeArea_mm2: 1.28; SizeX_mm: 1.6; SizeY_mm: 0.8; SizeZ_mm: 1; EIA_Code: E192; U/M: EA; AEC Category: Q200
signal-integrity model Resistor
simulation model Resistor
footprint 0603
footprint 0603M
footprint 0603L
footprint 0603_HV
footprint 0603S
pins: 1, 2

## RT0603DRE0737R4L
designator R?  ValueDisplayed: 37.4  (hidden comment: RT0603DRE0737R4L)
RES, 37.4, 0.5%, 0.1 W, 0603; Manufacturer: Yageo America; CompType: Resistor; Value: 37.4; Value_Code: 37R4; Tolerance_%: 0.5; Power_W: 0.1; Value2: 0.1W; VDC_V: 75; TempCo: 50 ppm/C; SizeArea_mm2: 1.28; SizeX_mm: 1.6; SizeY_mm: 0.8; SizeZ_mm: 1; EIA_Code: E192; U/M: EA; AEC Category: Q200
signal-integrity model Resistor
simulation model Resistor
footprint 0603
footprint 0603M
footprint 0603L
footprint 0603_HV
footprint 0603S
pins: 1, 2

## RT0603DRE0737R9L
designator R?  ValueDisplayed: 37.9  (hidden comment: RT0603DRE0737R9L)
RES, 37.9, 0.5%, 0.1 W, 0603; Manufacturer: Yageo America; CompType: Resistor; Value: 37.9; Value_Code: 37R9; Tolerance_%: 0.5; Power_W: 0.1; Value2: 0.1W; VDC_V: 75; TempCo: 50 ppm/C; SizeArea_mm2: 1.28; SizeX_mm: 1.6; SizeY_mm: 0.8; SizeZ_mm: 1; EIA_Code: E192; U/M: EA; AEC Category: Q200
signal-integrity model Resistor
simulation model Resistor
footprint 0603
footprint 0603M
footprint 0603L
footprint 0603_HV
footprint 0603S
pins: 1, 2

## RT0603DRE0737RL
designator R?  ValueDisplayed: 37.0  (hidden comment: RT0603DRE0737RL)
RES, 37.0, 0.5%, 0.1 W, 0603; Manufacturer: Yageo America; CompType: Resistor; Value: 37.0; Res_ohm: 37; Value_Code: 37R0; Tolerance_%: 0.5; Power_W: 0.1; Value2: 0.1W; VDC_V: 75; TempCo: 50 ppm/C; SizeArea_mm2: 1.28; SizeX_mm: 1.6; SizeY_mm: 0.8; SizeZ_mm: 1; EIA_Code: E192; U/M: EA; AEC Category: Q200
signal-integrity model Resistor
simulation model Resistor
footprint 0603
footprint 0603M
footprint 0603L
footprint 0603_HV
footprint 0603S
pins: 1, 2

## RT0603DRE0738K3L
designator R?  ValueDisplayed: 38.3k  (hidden comment: RT0603DRE0738K3L)
RES, 38.3 k, 0.5%, 0.1 W, 0603; Manufacturer: Yageo America; CompType: Resistor; Value: 38.3k; Res_ohm: 38300; Value_Code: 38k3; Tolerance_%: 0.5; Power_W: 0.1; Value2: 0.1W; VDC_V: 75; TempCo: 50 ppm/C; SizeArea_mm2: 1.28; SizeX_mm: 1.6; SizeY_mm: 0.8; SizeZ_mm: 1; EIA_Code: E192; U/M: EA; AEC Category: Q200
signal-integrity model Resistor
simulation model Resistor
footprint 0603
footprint 0603M
footprint 0603L
footprint 0603_HV
footprint 0603S
pins: 1, 2

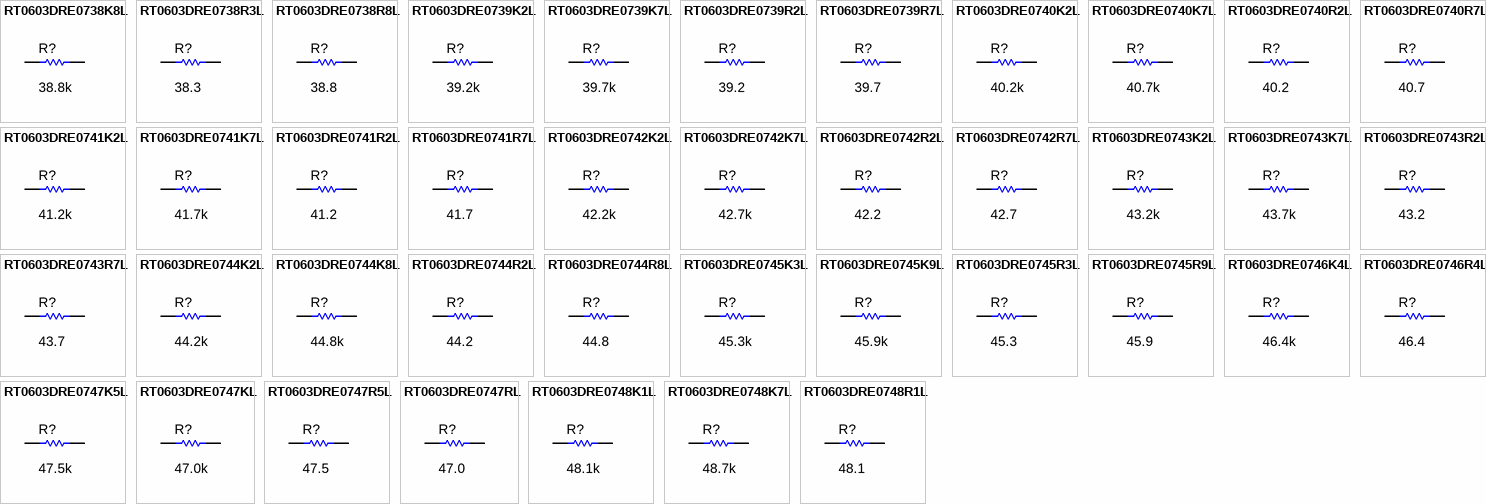
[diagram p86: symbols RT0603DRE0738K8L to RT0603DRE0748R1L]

## RT0603DRE0738K8L
designator R?  ValueDisplayed: 38.8k  (hidden comment: RT0603DRE0738K8L)
RES, 38.8 k, 0.5%, 0.1 W, 0603; Manufacturer: Yageo America; CompType: Resistor; Value: 38.8k; Res_ohm: 38800; Value_Code: 38k8; Tolerance_%: 0.5; Power_W: 0.1; Value2: 0.1W; VDC_V: 75; TempCo: 50 ppm/C; SizeArea_mm2: 1.28; SizeX_mm: 1.6; SizeY_mm: 0.8; SizeZ_mm: 1; EIA_Code: E192; U/M: EA; AEC Category: Q200
signal-integrity model Resistor
simulation model Resistor
footprint 0603
footprint 0603M
footprint 0603L
footprint 0603_HV
footprint 0603S
pins: 1, 2

## RT0603DRE0738R3L
designator R?  ValueDisplayed: 38.3  (hidden comment: RT0603DRE0738R3L)
RES, 38.3, 0.5%, 0.1 W, 0603; Manufacturer: Yageo America; CompType: Resistor; Value: 38.3; Value_Code: 38R3; Tolerance_%: 0.5; Power_W: 0.1; Value2: 0.1W; VDC_V: 75; TempCo: 50 ppm/C; SizeArea_mm2: 1.28; SizeX_mm: 1.6; SizeY_mm: 0.8; SizeZ_mm: 1; EIA_Code: E192; U/M: EA; AEC Category: Q200
signal-integrity model Resistor
simulation model Resistor
footprint 0603
footprint 0603M
footprint 0603L
footprint 0603_HV
footprint 0603S
pins: 1, 2

## RT0603DRE0738R8L
designator R?  ValueDisplayed: 38.8  (hidden comment: RT0603DRE0738R8L)
RES, 38.8, 0.5%, 0.1 W, 0603; Manufacturer: Yageo America; CompType: Resistor; Value: 38.8; Value_Code: 38R8; Tolerance_%: 0.5; Power_W: 0.1; Value2: 0.1W; VDC_V: 75; TempCo: 50 ppm/C; SizeArea_mm2: 1.28; SizeX_mm: 1.6; SizeY_mm: 0.8; SizeZ_mm: 1; EIA_Code: E192; U/M: EA; AEC Category: Q200
signal-integrity model Resistor
simulation model Resistor
footprint 0603
footprint 0603M
footprint 0603L
footprint 0603_HV
footprint 0603S
pins: 1, 2

## RT0603DRE0739K2L
designator R?  ValueDisplayed: 39.2k  (hidden comment: RT0603DRE0739K2L)
RES, 39.2 k, 0.5%, 0.1 W, 0603; Manufacturer: Yageo America; CompType: Resistor; Value: 39.2k; Res_ohm: 39200; Value_Code: 39k2; Tolerance_%: 0.5; Power_W: 0.1; Value2: 0.1W; VDC_V: 75; TempCo: 50 ppm/C; SizeArea_mm2: 1.28; SizeX_mm: 1.6; SizeY_mm: 0.8; SizeZ_mm: 1; EIA_Code: E192; U/M: EA; AEC Category: Q200
signal-integrity model Resistor
simulation model Resistor
footprint 0603
footprint 0603M
footprint 0603L
footprint 0603_HV
footprint 0603S
pins: 1, 2

## RT0603DRE0739K7L
designator R?  ValueDisplayed: 39.7k  (hidden comment: RT0603DRE0739K7L)
RES, 39.7 k, 0.5%, 0.1 W, 0603; Manufacturer: Yageo America; CompType: Resistor; Value: 39.7k; Res_ohm: 39700; Value_Code: 39k7; Tolerance_%: 0.5; Power_W: 0.1; Value2: 0.1W; VDC_V: 75; TempCo: 50 ppm/C; SizeArea_mm2: 1.28; SizeX_mm: 1.6; SizeY_mm: 0.8; SizeZ_mm: 1; EIA_Code: E192; U/M: EA; AEC Category: Q200
signal-integrity model Resistor
simulation model Resistor
footprint 0603
footprint 0603M
footprint 0603L
footprint 0603_HV
footprint 0603S
pins: 1, 2

## RT0603DRE0739R2L
designator R?  ValueDisplayed: 39.2  (hidden comment: RT0603DRE0739R2L)
RES, 39.2, 0.5%, 0.1 W, 0603; Manufacturer: Yageo America; CompType: Resistor; Value: 39.2; Value_Code: 39R2; Tolerance_%: 0.5; Power_W: 0.1; Value2: 0.1W; VDC_V: 75; TempCo: 50 ppm/C; SizeArea_mm2: 1.28; SizeX_mm: 1.6; SizeY_mm: 0.8; SizeZ_mm: 1; EIA_Code: E192; U/M: EA; AEC Category: Q200
signal-integrity model Resistor
simulation model Resistor
footprint 0603
footprint 0603M
footprint 0603L
footprint 0603_HV
footprint 0603S
pins: 1, 2

## RT0603DRE0739R7L
designator R?  ValueDisplayed: 39.7  (hidden comment: RT0603DRE0739R7L)
RES, 39.7, 0.5%, 0.1 W, 0603; Manufacturer: Yageo America; CompType: Resistor; Value: 39.7; Value_Code: 39R7; Tolerance_%: 0.5; Power_W: 0.1; Value2: 0.1W; VDC_V: 75; TempCo: 50 ppm/C; SizeArea_mm2: 1.28; SizeX_mm: 1.6; SizeY_mm: 0.8; SizeZ_mm: 1; EIA_Code: E192; U/M: EA; AEC Category: Q200
signal-integrity model Resistor
simulation model Resistor
footprint 0603
footprint 0603M
footprint 0603L
footprint 0603_HV
footprint 0603S
pins: 1, 2

## RT0603DRE0740K2L
designator R?  ValueDisplayed: 40.2k  (hidden comment: RT0603DRE0740K2L)
RES, 40.2 k, 0.5%, 0.1 W, 0603; Manufacturer: Yageo America; CompType: Resistor; Value: 40.2k; Res_ohm: 40200; Value_Code: 40k2; Tolerance_%: 0.5; Power_W: 0.1; Value2: 0.1W; VDC_V: 75; TempCo: 50 ppm/C; SizeArea_mm2: 1.28; SizeX_mm: 1.6; SizeY_mm: 0.8; SizeZ_mm: 1; EIA_Code: E192; U/M: EA; AEC Category: Q200
signal-integrity model Resistor
simulation model Resistor
footprint 0603
footprint 0603M
footprint 0603L
footprint 0603_HV
footprint 0603S
pins: 1, 2

## RT0603DRE0740K7L
designator R?  ValueDisplayed: 40.7k  (hidden comment: RT0603DRE0740K7L)
RES, 40.7 k, 0.5%, 0.1 W, 0603; Manufacturer: Yageo America; CompType: Resistor; Value: 40.7k; Res_ohm: 40700; Value_Code: 40k7; Tolerance_%: 0.5; Power_W: 0.1; Value2: 0.1W; VDC_V: 75; TempCo: 50 ppm/C; SizeArea_mm2: 1.28; SizeX_mm: 1.6; SizeY_mm: 0.8; SizeZ_mm: 1; EIA_Code: E192; U/M: EA; AEC Category: Q200
signal-integrity model Resistor
simulation model Resistor
footprint 0603
footprint 0603M
footprint 0603L
footprint 0603_HV
footprint 0603S
pins: 1, 2

## RT0603DRE0740R2L
designator R?  ValueDisplayed: 40.2  (hidden comment: RT0603DRE0740R2L)
RES, 40.2, 0.5%, 0.1 W, 0603; Manufacturer: Yageo America; CompType: Resistor; Value: 40.2; Value_Code: 40R2; Tolerance_%: 0.5; Power_W: 0.1; Value2: 0.1W; VDC_V: 75; TempCo: 50 ppm/C; SizeArea_mm2: 1.28; SizeX_mm: 1.6; SizeY_mm: 0.8; SizeZ_mm: 1; EIA_Code: E192; U/M: EA; AEC Category: Q200
signal-integrity model Resistor
simulation model Resistor
footprint 0603
footprint 0603M
footprint 0603L
footprint 0603_HV
footprint 0603S
pins: 1, 2

## RT0603DRE0740R7L
designator R?  ValueDisplayed: 40.7  (hidden comment: RT0603DRE0740R7L)
RES, 40.7, 0.5%, 0.1 W, 0603; Manufacturer: Yageo America; CompType: Resistor; Value: 40.7; Value_Code: 40R7; Tolerance_%: 0.5; Power_W: 0.1; Value2: 0.1W; VDC_V: 75; TempCo: 50 ppm/C; SizeArea_mm2: 1.28; SizeX_mm: 1.6; SizeY_mm: 0.8; SizeZ_mm: 1; EIA_Code: E192; U/M: EA; AEC Category: Q200
signal-integrity model Resistor
simulation model Resistor
footprint 0603
footprint 0603M
footprint 0603L
footprint 0603_HV
footprint 0603S
pins: 1, 2

## RT0603DRE0741K2L
designator R?  ValueDisplayed: 41.2k  (hidden comment: RT0603DRE0741K2L)
RES, 41.2 k, 0.5%, 0.1 W, 0603; Manufacturer: Yageo America; CompType: Resistor; Value: 41.2k; Res_ohm: 41200; Value_Code: 41k2; Tolerance_%: 0.5; Power_W: 0.1; Value2: 0.1W; VDC_V: 75; TempCo: 50 ppm/C; SizeArea_mm2: 1.28; SizeX_mm: 1.6; SizeY_mm: 0.8; SizeZ_mm: 1; EIA_Code: E192; U/M: EA; AEC Category: Q200
signal-integrity model Resistor
simulation model Resistor
footprint 0603
footprint 0603M
footprint 0603L
footprint 0603_HV
footprint 0603S
pins: 1, 2

## RT0603DRE0741K7L
designator R?  ValueDisplayed: 41.7k  (hidden comment: RT0603DRE0741K7L)
RES, 41.7 k, 0.5%, 0.1 W, 0603; Manufacturer: Yageo America; CompType: Resistor; Value: 41.7k; Res_ohm: 41700; Value_Code: 41k7; Tolerance_%: 0.5; Power_W: 0.1; Value2: 0.1W; VDC_V: 75; TempCo: 50 ppm/C; SizeArea_mm2: 1.28; SizeX_mm: 1.6; SizeY_mm: 0.8; SizeZ_mm: 1; EIA_Code: E192; U/M: EA; AEC Category: Q200
signal-integrity model Resistor
simulation model Resistor
footprint 0603
footprint 0603M
footprint 0603L
footprint 0603_HV
footprint 0603S
pins: 1, 2

## RT0603DRE0741R2L
designator R?  ValueDisplayed: 41.2  (hidden comment: RT0603DRE0741R2L)
RES, 41.2, 0.5%, 0.1 W, 0603; Manufacturer: Yageo America; CompType: Resistor; Value: 41.2; Value_Code: 41R2; Tolerance_%: 0.5; Power_W: 0.1; Value2: 0.1W; VDC_V: 75; TempCo: 50 ppm/C; SizeArea_mm2: 1.28; SizeX_mm: 1.6; SizeY_mm: 0.8; SizeZ_mm: 1; EIA_Code: E192; U/M: EA; AEC Category: Q200
signal-integrity model Resistor
simulation model Resistor
footprint 0603
footprint 0603M
footprint 0603L
footprint 0603_HV
footprint 0603S
pins: 1, 2

## RT0603DRE0741R7L
designator R?  ValueDisplayed: 41.7  (hidden comment: RT0603DRE0741R7L)
RES, 41.7, 0.5%, 0.1 W, 0603; Manufacturer: Yageo America; CompType: Resistor; Value: 41.7; Value_Code: 41R7; Tolerance_%: 0.5; Power_W: 0.1; Value2: 0.1W; VDC_V: 75; TempCo: 50 ppm/C; SizeArea_mm2: 1.28; SizeX_mm: 1.6; SizeY_mm: 0.8; SizeZ_mm: 1; EIA_Code: E192; U/M: EA; AEC Category: Q200
signal-integrity model Resistor
simulation model Resistor
footprint 0603
footprint 0603M
footprint 0603L
footprint 0603_HV
footprint 0603S
pins: 1, 2

## RT0603DRE0742K2L
designator R?  ValueDisplayed: 42.2k  (hidden comment: RT0603DRE0742K2L)
RES, 42.2 k, 0.5%, 0.1 W, 0603; Manufacturer: Yageo America; CompType: Resistor; Value: 42.2k; Res_ohm: 42200; Value_Code: 42k2; Tolerance_%: 0.5; Power_W: 0.1; Value2: 0.1W; VDC_V: 75; TempCo: 50 ppm/C; SizeArea_mm2: 1.28; SizeX_mm: 1.6; SizeY_mm: 0.8; SizeZ_mm: 1; EIA_Code: E192; U/M: EA; AEC Category: Q200
signal-integrity model Resistor
simulation model Resistor
footprint 0603
footprint 0603M
footprint 0603L
footprint 0603_HV
footprint 0603S
pins: 1, 2

## RT0603DRE0742K7L
designator R?  ValueDisplayed: 42.7k  (hidden comment: RT0603DRE0742K7L)
RES, 42.7 k, 0.5%, 0.1 W, 0603; Manufacturer: Yageo America; CompType: Resistor; Value: 42.7k; Res_ohm: 42700; Value_Code: 42k7; Tolerance_%: 0.5; Power_W: 0.1; Value2: 0.1W; VDC_V: 75; TempCo: 50 ppm/C; SizeArea_mm2: 1.28; SizeX_mm: 1.6; SizeY_mm: 0.8; SizeZ_mm: 1; EIA_Code: E192; U/M: EA; AEC Category: Q200
signal-integrity model Resistor
simulation model Resistor
footprint 0603
footprint 0603M
footprint 0603L
footprint 0603_HV
footprint 0603S
pins: 1, 2

## RT0603DRE0742R2L
designator R?  ValueDisplayed: 42.2  (hidden comment: RT0603DRE0742R2L)
RES, 42.2, 0.5%, 0.1 W, 0603; Manufacturer: Yageo America; CompType: Resistor; Value: 42.2; Value_Code: 42R2; Tolerance_%: 0.5; Power_W: 0.1; Value2: 0.1W; VDC_V: 75; TempCo: 50 ppm/C; SizeArea_mm2: 1.28; SizeX_mm: 1.6; SizeY_mm: 0.8; SizeZ_mm: 1; EIA_Code: E192; U/M: EA; AEC Category: Q200
signal-integrity model Resistor
simulation model Resistor
footprint 0603
footprint 0603M
footprint 0603L
footprint 0603_HV
footprint 0603S
pins: 1, 2

## RT0603DRE0742R7L
designator R?  ValueDisplayed: 42.7  (hidden comment: RT0603DRE0742R7L)
RES, 42.7, 0.5%, 0.1 W, 0603; Manufacturer: Yageo America; CompType: Resistor; Value: 42.7; Value_Code: 42R7; Tolerance_%: 0.5; Power_W: 0.1; Value2: 0.1W; VDC_V: 75; TempCo: 50 ppm/C; SizeArea_mm2: 1.28; SizeX_mm: 1.6; SizeY_mm: 0.8; SizeZ_mm: 1; EIA_Code: E192; U/M: EA; AEC Category: Q200
signal-integrity model Resistor
simulation model Resistor
footprint 0603
footprint 0603M
footprint 0603L
footprint 0603_HV
footprint 0603S
pins: 1, 2

## RT0603DRE0743K2L
designator R?  ValueDisplayed: 43.2k  (hidden comment: RT0603DRE0743K2L)
RES, 43.2 k, 0.5%, 0.1 W, 0603; Manufacturer: Yageo America; CompType: Resistor; Value: 43.2k; Res_ohm: 43200; Value_Code: 43k2; Tolerance_%: 0.5; Power_W: 0.1; Value2: 0.1W; VDC_V: 75; TempCo: 50 ppm/C; SizeArea_mm2: 1.28; SizeX_mm: 1.6; SizeY_mm: 0.8; SizeZ_mm: 1; EIA_Code: E192; U/M: EA; AEC Category: Q200
signal-integrity model Resistor
simulation model Resistor
footprint 0603
footprint 0603M
footprint 0603L
footprint 0603_HV
footprint 0603S
pins: 1, 2

## RT0603DRE0743K7L
designator R?  ValueDisplayed: 43.7k  (hidden comment: RT0603DRE0743K7L)
RES, 43.7 k, 0.5%, 0.1 W, 0603; Manufacturer: Yageo America; CompType: Resistor; Value: 43.7k; Res_ohm: 43700; Value_Code: 43k7; Tolerance_%: 0.5; Power_W: 0.1; Value2: 0.1W; VDC_V: 75; TempCo: 50 ppm/C; SizeArea_mm2: 1.28; SizeX_mm: 1.6; SizeY_mm: 0.8; SizeZ_mm: 1; EIA_Code: E192; U/M: EA; AEC Category: Q200
signal-integrity model Resistor
simulation model Resistor
footprint 0603
footprint 0603M
footprint 0603L
footprint 0603_HV
footprint 0603S
pins: 1, 2

## RT0603DRE0743R2L
designator R?  ValueDisplayed: 43.2  (hidden comment: RT0603DRE0743R2L)
RES, 43.2, 0.5%, 0.1 W, 0603; Manufacturer: Yageo America; CompType: Resistor; Value: 43.2; Value_Code: 43R2; Tolerance_%: 0.5; Power_W: 0.1; Value2: 0.1W; VDC_V: 75; TempCo: 50 ppm/C; SizeArea_mm2: 1.28; SizeX_mm: 1.6; SizeY_mm: 0.8; SizeZ_mm: 1; EIA_Code: E192; U/M: EA; AEC Category: Q200
signal-integrity model Resistor
simulation model Resistor
footprint 0603
footprint 0603M
footprint 0603L
footprint 0603_HV
footprint 0603S
pins: 1, 2

## RT0603DRE0743R7L
designator R?  ValueDisplayed: 43.7  (hidden comment: RT0603DRE0743R7L)
RES, 43.7, 0.5%, 0.1 W, 0603; Manufacturer: Yageo America; CompType: Resistor; Value: 43.7; Value_Code: 43R7; Tolerance_%: 0.5; Power_W: 0.1; Value2: 0.1W; VDC_V: 75; TempCo: 50 ppm/C; SizeArea_mm2: 1.28; SizeX_mm: 1.6; SizeY_mm: 0.8; SizeZ_mm: 1; EIA_Code: E192; U/M: EA; AEC Category: Q200
signal-integrity model Resistor
simulation model Resistor
footprint 0603
footprint 0603M
footprint 0603L
footprint 0603_HV
footprint 0603S
pins: 1, 2

## RT0603DRE0744K2L
designator R?  ValueDisplayed: 44.2k  (hidden comment: RT0603DRE0744K2L)
RES, 44.2 k, 0.5%, 0.1 W, 0603; Manufacturer: Yageo America; CompType: Resistor; Value: 44.2k; Res_ohm: 44200; Value_Code: 44k2; Tolerance_%: 0.5; Power_W: 0.1; Value2: 0.1W; VDC_V: 75; TempCo: 50 ppm/C; SizeArea_mm2: 1.28; SizeX_mm: 1.6; SizeY_mm: 0.8; SizeZ_mm: 1; EIA_Code: E192; U/M: EA; AEC Category: Q200
signal-integrity model Resistor
simulation model Resistor
footprint 0603
footprint 0603M
footprint 0603L
footprint 0603_HV
footprint 0603S
pins: 1, 2

## RT0603DRE0744K8L
designator R?  ValueDisplayed: 44.8k  (hidden comment: RT0603DRE0744K8L)
RES, 44.8 k, 0.5%, 0.1 W, 0603; Manufacturer: Yageo America; CompType: Resistor; Value: 44.8k; Res_ohm: 44800; Value_Code: 44k8; Tolerance_%: 0.5; Power_W: 0.1; Value2: 0.1W; VDC_V: 75; TempCo: 50 ppm/C; SizeArea_mm2: 1.28; SizeX_mm: 1.6; SizeY_mm: 0.8; SizeZ_mm: 1; EIA_Code: E192; U/M: EA; AEC Category: Q200
signal-integrity model Resistor
simulation model Resistor
footprint 0603
footprint 0603M
footprint 0603L
footprint 0603_HV
footprint 0603S
pins: 1, 2

## RT0603DRE0744R2L
designator R?  ValueDisplayed: 44.2  (hidden comment: RT0603DRE0744R2L)
RES, 44.2, 0.5%, 0.1 W, 0603; Manufacturer: Yageo America; CompType: Resistor; Value: 44.2; Value_Code: 44R2; Tolerance_%: 0.5; Power_W: 0.1; Value2: 0.1W; VDC_V: 75; TempCo: 50 ppm/C; SizeArea_mm2: 1.28; SizeX_mm: 1.6; SizeY_mm: 0.8; SizeZ_mm: 1; EIA_Code: E192; U/M: EA; AEC Category: Q200
signal-integrity model Resistor
simulation model Resistor
footprint 0603
footprint 0603M
footprint 0603L
footprint 0603_HV
footprint 0603S
pins: 1, 2

## RT0603DRE0744R8L
designator R?  ValueDisplayed: 44.8  (hidden comment: RT0603DRE0744R8L)
RES, 44.8, 0.5%, 0.1 W, 0603; Manufacturer: Yageo America; CompType: Resistor; Value: 44.8; Value_Code: 44R8; Tolerance_%: 0.5; Power_W: 0.1; Value2: 0.1W; VDC_V: 75; TempCo: 50 ppm/C; SizeArea_mm2: 1.28; SizeX_mm: 1.6; SizeY_mm: 0.8; SizeZ_mm: 1; EIA_Code: E192; U/M: EA; AEC Category: Q200
signal-integrity model Resistor
simulation model Resistor
footprint 0603
footprint 0603M
footprint 0603L
footprint 0603_HV
footprint 0603S
pins: 1, 2

## RT0603DRE0745K3L
designator R?  ValueDisplayed: 45.3k  (hidden comment: RT0603DRE0745K3L)
RES, 45.3 k, 0.5%, 0.1 W, 0603; Manufacturer: Yageo America; CompType: Resistor; Value: 45.3k; Res_ohm: 45300; Value_Code: 45k3; Tolerance_%: 0.5; Power_W: 0.1; Value2: 0.1W; VDC_V: 75; TempCo: 50 ppm/C; SizeArea_mm2: 1.28; SizeX_mm: 1.6; SizeY_mm: 0.8; SizeZ_mm: 1; EIA_Code: E192; U/M: EA; AEC Category: Q200
signal-integrity model Resistor
simulation model Resistor
footprint 0603
footprint 0603M
footprint 0603L
footprint 0603_HV
footprint 0603S
pins: 1, 2

## RT0603DRE0745K9L
designator R?  ValueDisplayed: 45.9k  (hidden comment: RT0603DRE0745K9L)
RES, 45.9 k, 0.5%, 0.1 W, 0603; Manufacturer: Yageo America; CompType: Resistor; Value: 45.9k; Res_ohm: 45900; Value_Code: 45k9; Tolerance_%: 0.5; Power_W: 0.1; Value2: 0.1W; VDC_V: 75; TempCo: 50 ppm/C; SizeArea_mm2: 1.28; SizeX_mm: 1.6; SizeY_mm: 0.8; SizeZ_mm: 1; EIA_Code: E192; U/M: EA; AEC Category: Q200
signal-integrity model Resistor
simulation model Resistor
footprint 0603
footprint 0603M
footprint 0603L
footprint 0603_HV
footprint 0603S
pins: 1, 2

## RT0603DRE0745R3L
designator R?  ValueDisplayed: 45.3  (hidden comment: RT0603DRE0745R3L)
RES, 45.3, 0.5%, 0.1 W, 0603; Manufacturer: Yageo America; CompType: Resistor; Value: 45.3; Value_Code: 45R3; Tolerance_%: 0.5; Power_W: 0.1; Value2: 0.1W; VDC_V: 75; TempCo: 50 ppm/C; SizeArea_mm2: 1.28; SizeX_mm: 1.6; SizeY_mm: 0.8; SizeZ_mm: 1; EIA_Code: E192; U/M: EA; AEC Category: Q200
signal-integrity model Resistor
simulation model Resistor
footprint 0603
footprint 0603M
footprint 0603L
footprint 0603_HV
footprint 0603S
pins: 1, 2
